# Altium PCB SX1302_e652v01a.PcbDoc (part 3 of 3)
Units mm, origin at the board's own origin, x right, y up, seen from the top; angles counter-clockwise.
Board outline 70.5 x 56 mm, 6 copper layers (Top Layer, MidLayer1 - GND, MidLayer2, MidLayer3, MidLayer4, Bottom Layer), stack 0.992 mm thick; 264 components, 191 nets, 862 pads, 1252 vias.
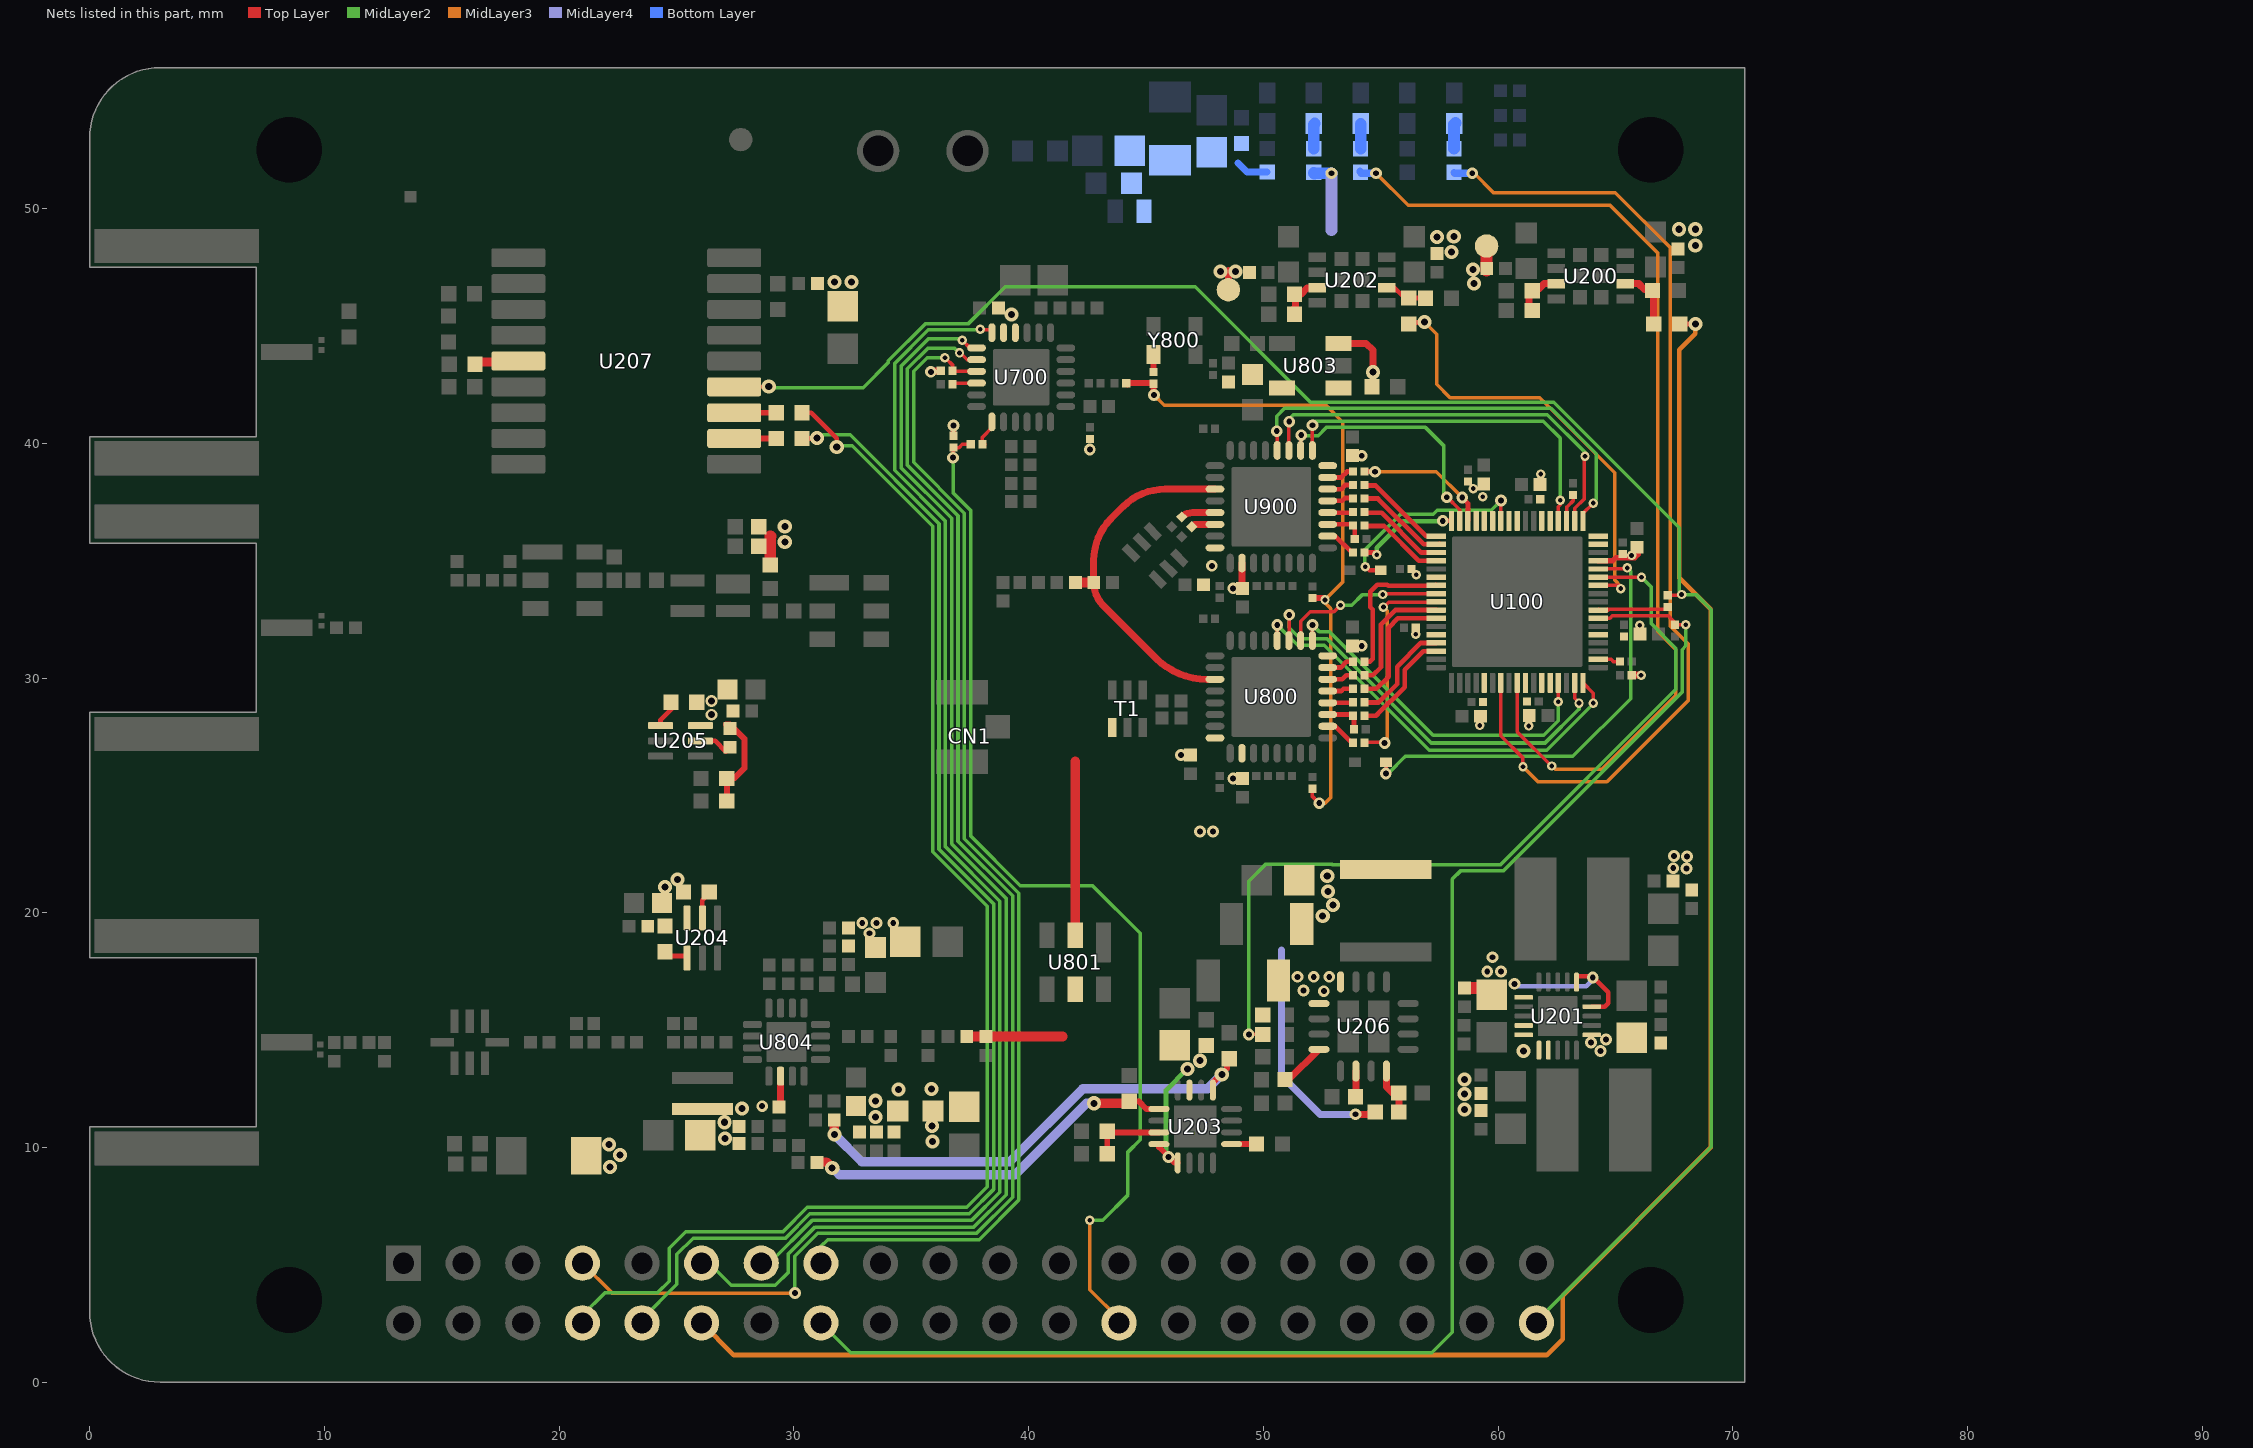
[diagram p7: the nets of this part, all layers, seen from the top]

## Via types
v1: diameter 0.6, hole 0.3, Top Layer to Bottom Layer, tented both sides, 827 vias
v2: diameter 0.5, hole 0.25, Top Layer to Bottom Layer, tented both sides, 168 vias
v3: diameter 0.6, hole 0.3, Top Layer to Bottom Layer, tented top, 86 vias
v4: diameter 0.4, hole 0.2, Top Layer to Bottom Layer, tented both sides, 59 vias
v5: diameter 0.6, hole 0.3, Top Layer to Bottom Layer, 48 vias
v6: diameter 0.6, hole 0.3, Top Layer to Bottom Layer, tented bottom, 21 vias
v7: diameter 0.5, hole 0.3, Top Layer to Bottom Layer, tented both sides, 18 vias
v8: diameter 0.5, hole 0.25, Top Layer to Bottom Layer, tented top, 16 vias
v9: diameter 0.5, hole 0.3, Top Layer to Bottom Layer, 5 vias
v10: diameter 0.5, hole 0.2, Top Layer to Bottom Layer, 4 vias

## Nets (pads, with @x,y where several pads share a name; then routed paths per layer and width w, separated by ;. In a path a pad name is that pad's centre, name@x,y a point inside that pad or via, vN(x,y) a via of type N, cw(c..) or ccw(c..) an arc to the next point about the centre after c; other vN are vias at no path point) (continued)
NetL800_2: L800.2 L801.1 U800.27 U900.27 | length 15.7
  Top Layer w0.3: L800.2@42.773,33.949 L800.2@42.773,34.073 ; U800.27@47.939,29.948 47.593,29.948 cw(c47.593,33.015) 45.425,30.847 43.18,33.091 cw(c44.162,34.073) L800.2@42.773,34.073 ; U900.27@47.939,38.048 45.816,38.048 ccw(c45.816,35.508) 44.02,37.305 43.517,36.802 ccw(c45.313,35.006) 42.773,35.006 L800.2@42.773,34.073
  Top Layer w0.42: L801.1@41.998,34.073 L800.2@42.773,34.073
NetR5_1: R5.1 R6.2 U206.4 | length 2.2
  Top Layer w0.3: U206.4@55.243,13.261 55.243,12.625 55.255,12.613 55.255,12.585 55.62,12.219 R6.2@55.77,12.219 ; R5.1@55.77,11.519 R6.2@55.77,12.219 ; R6.2@55.77,12.394 55.77,12.321 R6.2@55.77,12.219
NetR7_2: R7.2 U206.2 | length 1.1
  Top Layer w0.3: U206.2@53.943,13.261 53.943,12.249 R7.2@53.972,12.22
NetR8_2: R8.2 U206.16 | length 1.9
  Top Layer w0.3: R8.2@50.97,12.894 51.076,12.894 U206.16@52.368,14.186
NetR10_2: R10.2 R11.2 U801.5 | length 4.1
  Top Layer w0.42: R10.2@37.366,14.73 R11.2@38.191,14.729 41.455,14.73
NetR100_2: R100.2 U100.20 | length 1.2
  Top Layer w0.15: U100.20@62.915,36.698 62.915,37.266 62.985,37.336 62.985,37.339 63.192,37.546 R100.2@63.192,37.803
NetR102_1: R102.1 U100.2 | length 1
  Top Layer w0.15: U100.2@64.265,30.798 64.815,30.798 64.915,30.698 R102.1@65.19,30.698
NetR104_1: R104.1 TX_ON.1 | length 1.1
  Bottom Layer w0.5: R104.1@58.126,52.551 58.126,53.587 58.145,53.606 TX_ON.1@58.188,53.65
NetR106_1: R106.1 RX_ON.1 | length 1.1
  Bottom Layer w0.5: R106.1@54.143,52.551 54.143,53.592 RX_ON.1@54.15,53.599
NetR108_2: R108.2 U100.8 | length 3
  Top Layer w0.15: U100.8@64.29,32.923 U100.8@64.265,32.898 64.689,32.898 64.719,32.928 ; U100.8@64.644,32.93 64.645,32.928 64.719,32.928 ; R108.2@67.097,32.93 67.096,32.928 64.719,32.928
NetR110_1: R110.1 U100.44 | length 5.3
  Top Layer w0.2: R110.1@54.314,30.123 54.664,30.123 55.013,30.472 55.013,32.285 55.626,32.898 U100.44@57.365,32.898 U100.44@57.376,32.898
NetR111_1: R111.1 U100.45 | length 5.5
  Top Layer w0.2: R111.1@54.302,29.545 54.314,29.545 54.815,29.545 55.333,30.063 55.333,32.153 55.729,32.548 U100.45@57.365,32.548
NetR112_1: R112.1 U100.49 | length 4.7
  Top Layer w0.2: R112.1@54.314,28.398 54.806,28.398 54.861,28.453 ; 54.836,28.432 56.019,29.616 56.019,30.348 56.82,31.148 U100.49@57.365,31.148
NetR113_1: R113.1 U100.41 | length 6.3
  Top Layer w0.2: R113.1@54.314,30.698 54.542,30.698 54.659,30.816 54.659,32.922 54.556,33.025 54.556,33.685 54.849,33.978 55.279,33.978 55.318,33.939 U100.41@57.35,33.939 ; U100.41@57.35,33.963 U100.41@57.362,33.951
NetR114_1: R114.1 U100.48 | length 4.5
  Top Layer w0.2: R114.1@54.328,28.958 54.909,28.958 ; 54.912,28.961 55.699,29.748 55.699,30.485 56.712,31.498 U100.48@57.365,31.498
NetR115_1: R115.1 U100.43 | length 9.2
  Top Layer w0.15: R115.1@54.302,27.259 54.314,27.259 54.325,27.259 55.14,27.259 v2(55.166,27.234) ; v4(55.115,33.025) 55.14,33.025 55.344,33.228 57.365,33.228 57.376,33.228 57.38,33.233 U100.43@57.401,33.254
  Top Layer w0.2: R115.1@54.314,27.248 R115.1@54.325,27.259
  MidLayer3 w0.15: v4(55.115,33.025) 55.281,32.859 55.281,27.349 v2(55.166,27.234)
NetR120_1: R120.1 U100.35 | length 4
  Top Layer w0.2: R120.1@54.302,38.207 54.314,38.207 54.775,38.207 56.934,36.048 U100.35@57.365,36.048
NetR121_1: R121.1 U100.36 | length 4
  Top Layer w0.2: R121.1@54.302,37.648 R121.1@54.314,37.648 54.882,37.648 56.831,35.698 U100.36@57.365,35.698 57.5,35.698 U100.36@57.5,35.713
NetR122_1: R122.1 U100.38 | length 3.7
  Top Layer w0.2: R122.1@54.302,36.479 54.314,36.479 55.145,36.479 56.626,34.998 U100.38@57.365,34.998
NetR123_2: R123.2 U100.32 | length 5.7
  Top Layer w0.2: R123.2@54.314,38.798 v2@54.752,38.798 ; v2(58.471,37.692) 58.715,37.447 U100.32@58.715,36.698
  MidLayer2 w0.2: v2@54.734,38.816 v2@54.759,38.816
  MidLayer3 w0.15: v2(54.759,38.791) 57.372,38.791 v2(58.471,37.692)
NetR124_1: R124.1 U100.37 | length 3.8
  Top Layer w0.2: R124.1@54.314,37.073 R124.1@54.339,37.048 ; R124.1@54.328,37.038 55.039,37.038 56.729,35.348 U100.37@57.365,35.348
NetR125_2: R125.2 U100.34 | length 4.5
  Top Layer w0.2: R125.2@54.314,35.348 54.836,35.348 v4@54.874,35.348 ; v2@57.69,36.698 U100.34@58.015,36.698
  MidLayer2 w0.2: v4(54.836,35.26) 54.836,35.554 55.962,36.681 57.622,36.681 v2(57.64,36.698)
NetR200_1: R200.1 R202.2 U200.7 | length 1.9
  Top Layer w0.3: R202.2@61.313,45.835 61.313,46.505 R200.1@61.313,46.538 ; R200.1@61.313,46.585 61.451,46.585 61.746,46.585 61.96,46.799 U200.7@62.47,46.799
NetR201_1: R201.1 R207.2 U200.2 | length 2.8
  Top Layer w0.3: U200.2@65.42,46.799 65.991,46.799 66.24,46.55 66.579,46.55 R207.2@66.62,46.55 ; R207.2@66.62,46.566 R207.2@66.62,46.55 ; R201.1@66.621,45.105 66.62,45.107 66.62,46.512 R207.2@66.62,46.55 ; R207.2@66.672,46.55 R207.2@66.62,46.55
NetR203_1: R203.1 R206.2 U202.7 | length 1.8
  Top Layer w0.3: R206.2@51.203,45.633 51.377,45.806 51.377,46.353 51.377,46.368 51.619,46.368 51.864,46.613 52.283,46.613 U202.7@52.301,46.631
NetR204_1: R204.1 R213.2 U202.2 | length 1.9
  Top Layer w0.2: U202.2@55.251,46.631 55.583,46.631 55.937,46.277 R204.1@56.136,46.277 ; R204.1@56.115,46.314 56.215,46.213 56.241,46.187 56.739,46.187 56.821,46.269 R213.2@56.859,46.307
NetR205_1: R205.1 U204.2 | length 1.4
  Top Layer w0.2: U204.2@26.102,19.779 26.102,20.528 26.428,20.854 26.458,20.885 R205.1@26.572,20.885
NetR208_2: R208.2 VCCIO33.1 | length 1.1
  Bottom Layer w0.5: R208.2@52.152,52.551 52.152,53.582 52.173,53.604 VCCIO33.1@52.194,53.624
NetR211_1: R211.1 U207.3 | length 1.8
  Top Layer w0.25: U207.3@27.461,41.305 R211.1@29.245,41.305 29.263,41.305 cw(c29.263,41.272) R211.1@29.287,41.295
NetR212_1: R212.1 U207.2 | length 1.8
  Top Layer w0.25: U207.2@27.461,40.205 29.205,40.205 ccw(c29.205,40.285) R212.1@29.262,40.229
NetR214_1: R214.1 U205.4 | length 0.9
  Top Layer w0.2: U205.4@24.322,27.975 24.322,28.227 R214.1@24.792,28.697
NetR215_1: R215.1 U205.2 | length 1.3
  Top Layer w0.2: U205.2@26.022,27.325 26.645,27.325 27.099,26.871 R215.1@27.103,26.868
NetR216_1: R216.1 U204.4 | length 1
  Top Layer w0.2: R216.1@24.608,18.338 24.786,18.159 25.372,18.159 U204.4@25.452,18.079
NetR217_2: R217.2 U207.14 | length 1.8
  Top Layer w0.4: R217.2@16.466,43.463 18.261,43.463 U207.14@18.266,43.463
NetR218_2: R218.2 R219.1 U203.7 | length 3.1
  Top Layer w0.25: R219.1@43.352,9.783 43.349,9.786 43.349,10.64 43.356,10.647 U203.7@45.55,10.647
NetR220_1: R220.1 U203.13 | length 1.1
  Top Layer w0.2: R220.1@49.708,10.147 R220.1@49.712,10.15
  Top Layer w0.25: U203.13@48.65,10.147 R220.1@49.708,10.147
NetR704_1: R704.1 U700.16 | length 1
  Top Layer w0.15: R704.1@36.76,42.514 36.81,42.564 U700.16@37.785,42.564
NetR705_1: R705.1 U700.19 | length 1.1
  Top Layer w0.15: R705.1@38.035,39.964 38.035,40.264 38.435,40.664 U700.19@38.435,40.889 ; R705.1@38.135,39.939 R705.1@38.135,39.964
NetR815_2: R815.2 Y800.3 | length 0.7
  Top Layer w0.25: R815.2@45.314,43.091 Y800.3@45.314,43.788
POWER_EN: CN1.12 R201.2 | length 84.9
  Top Layer w0.2: R201.2@67.734,45.08 v1(68.403,45.08)
  MidLayer3 w0.2: CN1.12@26.071,2.535 27.442,1.163 62.078,1.163 62.75,1.835 62.75,3.692 69.063,10.006 69.063,32.936 67.72,34.279 67.72,43.985 68.403,44.668 v1(68.403,45.08)
PPS: CN1.40 R108.1 U207.4 | length 85.2
  Top Layer w0.15: U207.4@27.461,42.405 v1@28.898,42.405 ; R108.1@67.23,33.528 67.785,33.528 v4(67.815,33.558)
  MidLayer2 w0.15: v1@28.901,42.408 28.907,42.413 v1(28.931,42.413) ; v1@28.931,42.616 29.033,42.515 v1@29.18,42.368 ; v1@28.977,42.368 v1@29.18,42.368 ; CN1.40@61.647,2.484 61.647,2.535 61.647,2.613 69.075,10.041 69.075,32.915 68.432,33.558 v4@67.866,33.558 ; v4(67.815,33.558) v4@67.866,33.558 ; v1@29.18,42.368 32.949,42.368 34.025,43.443 34.025,43.513 35.615,45.103 37.442,45.103 39.01,46.67 47.097,46.67 52.01,41.757 62.363,41.757 67.717,36.403 67.717,33.707 67.84,33.584 v4@67.866,33.558
RADIO_A_CLK_32M: R115.2 U800.10 | length 1.3
  Top Layer w0.2: U800.10@52.739,27.948 53.064,27.948 R115.2@53.739,27.273
RADIO_A_CSN: U100.68 U800.20 | length 18.3
  Top Layer w0.15: U800.20@50.589,31.598 v2@50.589,32.263 ; U100.68@63.615,29.798 64.056,29.357 v4(64.056,28.936)
  MidLayer2 w0.15: v2@50.568,32.288 v2(50.594,32.263) 51.457,31.399 52.6,31.399 57.066,26.934 62.079,26.934 64.005,28.859 64.005,28.885 v4(64.056,28.936)
RADIO_A_IQ(0): R110.2 U800.14 | length 1.1
  Top Layer w0.2: U800.14@52.739,29.948 53.364,29.948 53.539,30.123 R110.2@53.814,30.123
RADIO_A_IQ(1): R111.2 U800.13 | length 1.1
  Top Layer w0.2: U800.13@52.739,29.448 53.314,29.448 53.414,29.548 R111.2@53.814,29.548
RADIO_A_IQ(2): R112.2 R813.1 U800.11 | length 1.7
  Top Layer w0.2: U800.11@52.739,28.448 53.764,28.448 R112.2@53.814,28.398 53.864,28.348 R813.1@53.864,27.823
RADIO_A_IQ(3): R113.2 U800.15 | length 1.2
  Top Layer w0.2: U800.15@52.739,30.448 53.289,30.448 53.539,30.698 R113.2@53.814,30.698
  Top Layer w0.25: U800.15@52.729,30.448 U800.15@52.739,30.448
RADIO_A_IQ(4): R114.2 U800.12 | length 1.1
  Top Layer w0.2: U800.12@52.739,28.948 53.789,28.948 R114.2@53.814,28.973
RADIO_A_MISO: U100.42 U800.18 | length 7.1
  Top Layer w0.15: U800.18@51.589,31.598 51.589,32.415 51.996,32.822 53.007,32.822 v4(53.286,33.101) ; v4(55.09,33.558) 55.129,33.598 U100.42@57.365,33.598
  MidLayer2 w0.15: v4(53.286,33.101) 53.769,33.101 54.226,33.558 v4(55.09,33.558) v4@55.115,33.558
RADIO_A_MOSI: U100.67 U800.19 | length 17.9
  Top Layer w0.15: U800.19@51.089,31.598 51.102,31.611 v2(51.102,32.695) 51.102,32.822 v2@51.127,32.847 ; U100.67@63.265,29.798 63.265,29.142 v4@63.421,28.986
  MidLayer2 w0.15: v2@51.089,32.708 v2(51.102,32.695) 51.102,32.137 51.569,31.669 52.712,31.669 57.147,27.235 61.999,27.235 63.44,28.676 ; 63.446,28.683 v4(63.446,28.936)
RADIO_A_RESET: D800.2 U100.13 | length 19.1
  Top Layer w0.15: v2@55.228,25.976 D800.2@55.228,26.408 ; U100.13@64.265,34.648 65.453,34.648 65.495,34.69 v4(65.495,34.693)
  MidLayer2 w0.15: v2(55.217,25.938) 55.318,25.938 56.045,26.665 ; 56.011,26.635 56.041,26.665 56.045,26.665 ; v4(65.495,34.693) 65.645,34.543 65.645,29.123 63.186,26.664 56.954,26.664 56.953,26.665 56.045,26.665
RADIO_A_SCK: U100.65 U800.17 | length 14.9
  Top Layer w0.15: U800.17@52.089,31.598 v2@52.089,32.223 ; v4@62.565,29.023 U100.65@62.565,29.798
  MidLayer2 w0.15: v2@52.118,32.288 v2(52.092,32.263) 52.372,31.984 52.804,31.984 57.227,27.56 61.942,27.56 62.557,28.175 v4(62.557,28.986)
RADIO_B_CLK_32M: R125.1 U900.10 | length 1.4
  Top Layer w0.2: U900.10@52.739,36.048 53.064,36.048 53.739,35.373 R125.1@53.814,35.373
RADIO_B_CSN: U100.18 U900.20 | length 19.3
  Top Layer w0.15: U900.20@50.589,39.698 50.589,40.518 v2@50.589,40.605 ; U100.18@63.615,36.698 63.615,37.019 v4(64.051,37.455)
  MidLayer2 w0.15: v2(50.568,40.518) 50.568,41.153 50.902,41.487 62.251,41.487 64.183,39.555 64.183,37.587 v4(64.051,37.455) ; v4(64.051,37.455) 64.023,37.427 63.995,37.455 v4(64.051,37.455)
RADIO_B_IQ(0): R120.2 U900.14 | length 1.1
  Top Layer w0.2: U900.14@52.739,38.048 53.314,38.048 53.489,38.223 R120.2@53.814,38.223
RADIO_B_IQ(1): R121.2 U900.13 | length 1.1
  Top Layer w0.2: U900.13@52.739,37.548 53.364,37.548 53.489,37.673 R121.2@53.814,37.673
RADIO_B_IQ(2): R122.2 R814.1 U900.11 | length 1.7
  Top Layer w0.2: U900.11@52.739,36.548 53.764,36.548 R122.2@53.814,36.498 53.889,36.423 R814.1@53.889,35.923
RADIO_B_IQ(3): R123.1 U900.15 | length 1.2
  Top Layer w0.2: U900.15@52.739,38.548 53.314,38.548 53.564,38.798 R123.1@53.814,38.798
  Top Layer w0.25: U900.15@52.714,38.548 U900.15@52.739,38.548
RADIO_B_IQ(4): R124.2 U900.12 | length 1.1
  Top Layer w0.2: U900.12@52.739,37.048 53.789,37.048 R124.2@53.814,37.073
RADIO_B_MISO: U100.33 U900.18 | length 10.7
  Top Layer w0.15: U900.18@51.589,39.698 v2@51.589,40.323 ; v2@57.821,37.712 58.36,37.173 58.365,37.173 U100.33@58.365,36.698
  MidLayer2 w0.15: v2(51.614,40.348) 51.636,40.327 52.331,40.327 52.681,40.677 56.904,40.677 57.693,39.888 57.693,37.827 v2(57.815,37.706)
RADIO_B_MOSI: U100.19 U900.19 | length 17.5
  Top Layer w0.15: U900.19@51.089,39.698 51.089,40.523 ; 51.089,40.473 v2@51.089,40.723 ; U100.19@63.265,36.698 63.265,37.228 63.665,37.628 v4@63.665,39.293
  MidLayer2 w0.15: v2(51.102,40.924) 51.102,41.051 51.267,41.217 62.101,41.217 63.7,39.617 v4(63.7,39.451)
RADIO_B_RESET: D900.2 U100.28 | length 9
  Top Layer w0.15: v4(54.339,34.748) 54.514,34.573 54.539,34.573 ; U100.28@60.115,36.698 60.115,37.555 v2(60.122,37.561)
  Top Layer w0.2: 54.539,34.598 D900.2@54.999,34.598
  MidLayer2 w0.15: v4@54.328,34.727 54.328,34.748 54.328,35.463 55.84,36.976 57.234,36.976 57.401,37.143 59.703,37.143 v2(60.122,37.561)
RADIO_B_SCK: U100.21 U900.17 | length 15.5
  Top Layer w0.15: U900.17@52.089,39.698 52.089,40.769 v2(52.092,40.772) ; U100.21@62.565,36.698 62.565,37.298 v4@62.651,37.384
  MidLayer2 w0.15: v2(52.092,40.772) 52.092,40.924 52.115,40.947 61.925,40.947 62.647,40.225 v4(62.647,37.58)
RADIO_CTRL(4): U100.16
RADIO_CTRL_(5): U100.17 | length 0.3
  Top Layer w0.15: U100.17@64.265,36.048 U100.17@64.615,36.048
RADIO_CTRL_(6): U100.22
RADIO_CTRL_(7): U100.26
RADIO_CTRL_(8): U100.27
RADIO_CTRL_(10): U100.29
RADIO_CTRL_(11): U100.31
RF_ON1: C810.1 U900.29 | length 1.5
  Top Layer w0.3: C810.1@46.525,36.863 cw(c46.973,36.416) 46.973,37.048 U900.29@47.939,37.048
RF_OP1: C809.1 U900.30 | length 1
  Top Layer w0.3: C809.1@46.944,36.453 cw(c47.174,36.223) 47.174,36.548 U900.30@47.939,36.548
RX_ON: R106.2 U100.60 | length 44.2
  Top Layer w0.15: U100.60@60.815,29.798 60.815,27.706 62.278,26.243 v4(62.291,26.255) ; v4@62.238,26.308 v4@62.291,26.256
  MidLayer3 w0.15: v2(54.801,51.505) 56.165,50.141 64.769,50.141 66.802,48.108 66.802,31.981 67.568,31.215 67.568,29.273 64.413,26.118 62.428,26.118 v4(62.291,26.255)
  Bottom Layer w0.3: R106.2@54.124,51.592 54.124,51.551 54.134,51.541 54.17,51.505 v2(54.801,51.505)
SX1261_BUSY: CN1.7 U700.14 | length 62.1
  Top Layer w0.15: v4(37.056,43.852) 37.091,43.852 37.38,43.564 U700.14@37.785,43.564
  MidLayer2 w0.15: v2(30.044,3.805) 30.04,3.809 30.04,5.37 31.015,6.346 37.782,6.346 39.317,7.881 39.317,20.723 36.993,23.047 36.993,36.917 34.835,39.075 34.835,43.177 35.699,44.041 36.858,44.041 37.051,43.848 37.056,43.843 v4(37.056,43.852)
  MidLayer3 w0.15: CN1.7@20.991,5.075 22.261,3.805 v2(30.044,3.805)
SX1261_DIO1: CN1.11 U700.13 | length 56.4
  Top Layer w0.15: v4(37.178,44.388) 37.502,44.064 U700.13@37.785,44.064
  MidLayer2 w0.15: CN1.11@26.071,5.075 26.391,5.075 27.336,4.13 29.206,4.13 29.77,4.694 29.77,5.482 30.903,6.616 37.67,6.616 39.047,7.993 39.047,20.611 36.723,22.935 36.723,36.805 34.565,38.963 34.565,43.289 35.721,44.445 37.121,44.445 v4(37.178,44.388)
SX1261_DIO2: CN1.13 U700.12 | length 53.5
  Top Layer w0.15: v4@37.935,44.831 37.944,44.831 38.435,44.831 38.45,44.831 U700.12@38.428,44.72
  MidLayer2 w0.15: CN1.13@28.601,5.075 CN1.13@28.611,5.075 28.957,5.075 30.796,6.914 37.586,6.914 38.777,8.105 38.777,20.499 36.453,22.824 36.453,36.694 34.295,38.851 34.295,43.401 35.727,44.833 37.917,44.833 v4(37.944,44.86)
SX1261_NRESET: CN1.15 R703.2 U700.15 | length 50.5
  Top Layer w0.15: v4(36.436,43.646) 36.452,43.646 36.509,43.589 v4@36.52,43.577 ; v4@36.51,43.589 36.76,43.339 R703.2@36.76,43.114 ; R703.2@36.76,43.089 R703.2@36.76,43.114 ; U700.15@37.785,43.064 36.81,43.064 36.772,43.102 R703.2@36.76,43.114
  MidLayer2 w0.15: CN1.15@31.151,5.075 31.151,5.79 31.437,6.076 37.894,6.076 39.587,7.769 39.587,20.835 37.263,23.159 37.263,37.029 35.105,39.187 35.105,43.065 35.686,43.646 v4(36.436,43.646)
SX1261_NSS: CN1.26 R702.2 R705.2 | length 45
  Top Layer w0.15: v2(36.78,39.39) 36.8,39.41 R702.2@36.8,39.826 ; R702.2@36.825,39.818 37.033,39.818 37.179,39.964 R705.2@37.535,39.964
  MidLayer2 w0.15: v2(36.78,39.39) 36.78,37.894 37.533,37.141 37.533,23.271 39.647,21.157 42.723,21.157 44.75,19.13 44.75,10.331 44.232,9.813 44.232,7.983 43.151,6.902 v4(42.61,6.902)
  MidLayer3 w0.15: v4@42.525,6.839 42.536,6.828 42.61,6.754 42.61,3.943 43.851,2.702 CN1.26@43.851,2.535 ; CN1.26@43.867,2.433 43.867,2.535 CN1.26@43.867,2.56
SX1302_LNA_REG_EN: R204.2 U100.11 | length 19
  Top Layer w0.15: U100.11@64.265,33.948 65.141,33.948 65.253,33.837 65.275,33.814 65.276,33.813 v4(65.229,33.813)
  Top Layer w0.2: R204.2@56.137,45.214 56.201,45.149 56.765,45.149 v1@56.805,45.19
  MidLayer2 w0.15: v1(56.868,45.164) v1@57.01,45.164
  MidLayer3 w0.15: v1(56.868,45.164) 57.384,44.647 57.384,42.511 57.951,41.944 61.766,41.944 64.964,38.746 64.964,34.177 65.229,33.912 v4(65.229,33.813) v4@65.252,33.837
SX1302_PA_REG_EN: R3.2 U100.12 | length 35.9
  Top Layer w0.15: v2(49.381,14.817) 49.382,14.819 R3.2@49.97,14.819 ; U100.12@64.265,34.298 v4(66.11,34.298)
  MidLayer2 w0.15: v2(49.381,14.817) 49.381,21.35 50.091,22.06 52.926,22.06 52.931,22.055 60.104,22.055 67.568,29.519 67.568,31.279 66.533,32.313 66.533,33.875 v4(66.11,34.298)
SX1302_RESET: CN1.16 R101.2 U100.7 | length 67
  Top Layer w0.15: U100.7@64.265,32.548 64.765,32.548 64.865,32.648 67.248,32.648 67.501,32.395 R101.2@67.501,32.33 ; R101.2@67.54,32.273 67.991,32.273 v4(67.997,32.278)
  MidLayer2 w0.15: CN1.16@31.151,2.535 32.427,1.259 57.174,1.259 58.05,2.135 58.05,21.44 58.395,21.785 60.216,21.785 67.838,29.407 67.838,31.215 67.997,31.373 v4(67.997,32.278)
SX1302_UART_RX: U100.64
SX1302_UART_TX: U100.63
TCXO_32M_O: C801.1 C901.2 R701.2 R815.1 | length 28.6
  Top Layer w0.15: C801.1@52.092,25.282 52.092,24.954 52.287,24.76 52.28,24.753 52.362,24.672 v2(52.381,24.672)
  Top Layer w0.25: R701.2@44.21,42.514 R701.2@44.16,42.564 45.291,42.564 R815.1@45.3,42.555 ; R815.1@45.259,42.514 R815.1@45.3,42.555 ; R815.1@45.309,42.564 R815.1@45.3,42.555 ; v2(45.341,42.061) 45.314,42.088 R815.1@45.314,42.54 R815.1@45.3,42.555 ; C901.2@52.118,33.406 52.524,33.406 52.613,33.317 v4@52.626,33.304
  MidLayer3 w0.15: v2(45.341,42.061) 45.785,41.618 52.671,41.618 53.388,40.9 53.388,34.093 v4(52.626,33.33) 52.626,33.203 52.867,32.962 52.867,24.912 52.626,24.672 v2(52.381,24.672)
TX_ON: R104.2 U100.58 | length 42.9
  Top Layer w0.15: U100.58@60.115,29.798 60.115,27.542 61.059,26.599 v4@61.059,26.243
  MidLayer3 w0.15: v2(58.901,51.505) 58.977,51.505 59.801,50.681 64.992,50.681 67.342,48.332 67.342,32.205 68.108,31.438 68.108,29.049 64.637,25.578 61.698,25.578 v4(61.059,26.218)
  Bottom Layer w0.3: R104.2@58.112,51.542 58.115,51.539 58.149,51.505 v2(58.901,51.505)
TX_PA: T1.1 U801.2 | length 7.4
  Top Layer w0.42: U801.2@41.987,19.045 41.987,26.44
UART_RXD_GPS: CN1.10 R212.2 | length 55
  Top Layer w0.2: R212.2@30.345,40.205 30.961,40.205 30.963,40.203 v1@30.989,40.178
  MidLayer2 w0.15: CN1.10@23.531,2.535 23.531,2.694 25.016,4.179 25.016,5.455 25.707,6.146 29.646,6.146 30.684,7.184 37.475,7.184 38.507,8.216 38.507,20.387 36.183,22.712 36.183,36.582 32.403,40.362 31.077,40.362 31.037,40.321 31.037,40.276 v1(30.989,40.229)
UART_TXD_GPS: CN1.8 R211.2 | length 57.6
  Top Layer w0.2: R211.2@30.345,41.305 30.738,41.305 31.827,40.216 v1(31.827,39.845)
  MidLayer2 w0.15: CN1.8@20.991,2.535 20.991,2.857 21.959,3.825 24.21,3.825 24.696,4.312 24.696,5.717 25.399,6.419 29.537,6.419 30.572,7.454 37.363,7.454 38.237,8.328 38.237,20.275 35.913,22.6 35.913,36.47 32.483,39.899 31.881,39.899 v1(31.827,39.845)
VCC5V: C8.2 C35.1 C47.1 C48.1 C201.1 C204.1 D2.2 D3.1 FB200.1 FB202.1 L8.2 R4.1 R14.2 R209.2 R210.2 RV1.2 U201.1 U201.4 U201.5 U201.6 U201.7 U201.11 U201.14 U201.16 U206.12 U206.13 | length 9.1
  Top Layer w0.2: U201.16@63.347,17.294 64.008,17.294 64.046,17.256 64.694,16.608 64.694,16.151 64.545,16.002 U201.14@63.989,16.002
  Top Layer w0.5: R209.2@58.564,16.801 59.739,16.801 59.802,16.801 C201.1@59.817,16.786
  MidLayer4 w0.2: v2(60.702,16.976) 60.808,16.871 63.75,16.871 64.033,17.154 v2(64.033,17.243)
  Bottom Layer w0.3: 48.917,51.948 49.31,51.555 R14.2@50.16,51.555
  other v1: 22.166,9.172 22.591,9.687 22.134,10.134 61.087,14.119 58.011,48.148 68.399,48.435 57.401,48.797 58.112,48.813 67.713,49.12 68.399,49.12
  other v2: 64.363,14.119 63.957,14.475 64.592,14.602 52.576,16.664 51.712,16.69 51.458,17.274 52.144,17.274 52.804,17.274 59.537,17.497 60.122,17.497 59.766,18.107
VCC_APC1: C210.1 R9.2 U203.1 | length 20.7
  Top Layer w0.25: U203.1@47.85,12.447 47.85,12.761 48.215,13.126 48.452,13.363 48.452,13.722 C210.1@48.517,13.787
  Top Layer w0.4: v1@31.719,10.568 R9.2@31.719,11.171
  MidLayer4 w0.4: v1(31.725,10.561) 32.89,9.397 39.201,9.397 42.312,12.508 47.625,12.508 v1(48.229,13.112)
VCC_APC2: C211.1 R1.2 U203.5 | length 16.2
  Top Layer w0.25: C211.1@44.283,11.972 44.691,11.972 45.016,11.647 U203.5@45.55,11.647
  Top Layer w0.4: R1.2@30.982,9.444 31.02,9.406 31.041,9.385 31.387,9.385 v1(31.634,9.139) ; v1(42.794,11.888) 44.199,11.888 C211.1@44.283,11.972
  MidLayer4 w0.4: v1(31.634,9.139) 31.931,8.843 39.42,8.843 42.465,11.888 v1(42.794,11.888)
VCCCORE12: C100.2 C101.2 C102.2 C103.2 C106.2 C108.2 C113.2 C221.2 FB208.2 U100.5 U100.23 U100.40 U100.56 | length 0.1
  Top Layer w0.23: C108.2@59.362,28.978 C108.2@59.415,29.031
  other v1: 58.56,11.618 58.56,12.279 58.56,12.896
  other v4: 59.215,27.985 66.04,32.248 56.512,34.397 61.822,38.69
VCCIO33: C104.2 C105.2 C107.2 C109.2 C110.2 C111.2 C112.2 C208.1 C209.1 C212.1 C213.1 C219.1 C220.2 C222.1 C223.1 FB1.1 FB207.2 R2.2 R15.2 R103.2 R205.2 R208.1 R214.2 R215.2 R216.2 U100.14 U100.30 U100.47 U100.61 U203.3 U203.8 U203.9 U204.3 U205.3 | length 15
  Top Layer w0.23: U203.8@45.55,10.147 45.55,10.016 46.219,9.347 U203.9@46.35,9.347 ; U100.14@64.265,34.998 64.883,34.998 65.013,35.128 65.819,35.128 65.972,35.281
  Top Layer w0.25: R2.2@27.103,25.903 R2.2@27.145,25.903 ; R215.2@27.103,28.028 27.28,28.028 27.893,27.415 27.893,26.161 27.482,25.751 27.145,25.751 R2.2@27.145,25.725 R15.2@27.145,24.815
  Top Layer w0.3: R103.2@65.69,30.123 v4@66.065,30.123
  MidLayer2 w0.2: v2(45.959,9.595) 45.855,9.698 45.855,12.449 v1(46.76,13.354)
  MidLayer4 w0.5: v2(52.901,51.505) 52.901,49.08 52.903,49.078
  Bottom Layer w0.5: R208.1@52.143,51.516 52.169,51.491 52.183,51.505 v2(52.901,51.505)
  other v1: 47.307,13.701 24.504,21.098 25.035,21.419 31.723,46.873 32.463,46.873
  other v2: 68.021,21.891 67.462,21.904 68.046,22.399 67.488,22.424 47.303,23.463 47.857,23.463
  other v4: 61.299,27.962 66.09,30.123 56.49,31.873 65.685,35.225 59.34,37.723 58.94,38.073
  other v7: 26.493,28.443 26.493,29.027
VDD_D_3.0_TCXO: C817.2 FB801.1 U803.5
VDD_RF_125x: C718.2 C800.2 C806.2 C808.2 C811.2 C900.2 C906.2 C908.2 FB201.2 P200.1 R702.1 R703.1 R713.1 U700.10 U700.11 U800.2 U800.16 U800.32 U803.1 U803.3 U900.2 U900.16 U900.32 | length 5.8
  Top Layer w0.2: R702.1@36.8,40.326 v2@36.8,40.733
  Top Layer w0.3: v2@35.86,43.089 R703.1@36.26,43.089 ; v2(48.714,33.823) C906.2@49.114,33.823 49.089,33.848 U900.2@49.089,34.898 ; U803.3@53.196,44.255 54.379,44.255 54.664,43.97 v1(54.664,43.029)
  Top Layer w0.5: FB201.2@59.509,47.365 59.509,47.452 P200.1@59.509,48.355
  other v1: 39.263,45.482 58.976,46.8 58.925,47.41
  other v2: 48.714,25.723 46.489,26.723 54.189,31.373 47.805,34.781 54.189,39.473 42.61,39.737 36.8,40.758 35.834,43.044
VDD_RF_LNA: C43.2 C44.2 FB203.2 L12.2 P201.1 | length 2.1
  Top Layer w0.3: P201.1@48.511,46.518 P201.1@48.511,46.538 48.511,47.318 48.511,47.363
  Top Layer w0.5: L12.2@28.997,34.813 28.997,35.621 28.997,36.041 29.004,36.048
  other v1: 29.613,35.794 29.613,36.454 48.181,47.318 48.816,47.318
VDD_RF_PA: C9.2 C10.2 C22.2 C37.2 C38.2 C39.2 L1.2 L2.1 L10.1 R5.2 | length 9.9
  Top Layer w0.3: C37.2@34.275,18.356 C37.2@34.287,18.344 ; v2@53.92,11.456 v2(53.92,11.419) 54.483,11.419 R5.2@54.573,11.508
  MidLayer4 w0.3: 50.778,18.406 50.778,13.059 52.418,11.419 v2(53.92,11.419)
  other v1: 35.913,10.267 35.887,10.927 35.862,12.502 52.528,19.861 52.96,20.328 52.746,20.917 52.721,21.565
  other v2: 33.22,19.13 32.915,19.563 33.525,19.563 34.236,19.563
VDDPA_A2: C12.2 C13.2 C14.2 C19.2 C23.2 C24.2 C25.2 L2.2 L3.2 L4.2 U804.14 | length 1.3
  Top Layer w0.3: C19.2@29.435,11.715 29.435,11.73 U804.14@29.435,13.045
  other v1: 27.073,10.394 27.048,11.079 33.474,11.308 27.785,11.664 33.474,11.994 34.465,12.476
  other v2: 28.648,11.765
pads on no net: "Fiducial Mark1.1" CN1.0 CN1.1 CN1.17 CN1.18 CN1.22 CN1.27 CN1.28 CN1.32 CN1.35 CN1.37 T1.6 T800.6 U100.10 U200.1 U200.4 U200.5 U202.1 U202.4 U202.5 U203.4 U203.15 U203.16 U207.5 U207.13 U207.15 U207.16 U207.17 U207.18 U700.4 U700.6 U700.23 U700.24 U800.6 U800.21 U800.22 U800.23 U800.24 U804.7 U804.13 U805.2 U805.6 U900.6 U900.21 U900.22 U900.23 U900.24

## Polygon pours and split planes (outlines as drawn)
VDD_RF_LNA on MidLayer4 "MidLayer3-No Net" (solid, pour order 200): 49.038,47.699 46.91,47.699 35.902,47.699 34.185,45.982 34.185,39.21 31.783,36.808 29.446,36.808 29.279,36.641 29.279,35.63 29.47,35.438 29.784,35.438 29.983,35.638 29.983,36.113 30.093,36.223 32.438,36.223 35.024,38.808 35.024,45.349 36.674,46.999 48.964,46.999 49.134,47.168 49.134,47.604
VDD_RF_PA on MidLayer4 "MidLayer4-No Net 1" (solid, pour order 70): 35.303,18.318 35.303,10.334 35.701,9.936 36.167,9.936 36.268,10.038 36.268,18.725 35.709,18.725
VDDPA_A2 on MidLayer4 "MidLayer4-No Net 1" (solid, pour order 68): 33.83,12.832 32.992,11.994 27.404,11.994 26.718,11.308 26.718,10.292 26.946,10.063 27.2,10.063 27.404,10.267 27.404,10.826 27.556,10.978 33.677,10.978 33.982,11.283 33.982,11.867 34.185,12.07 34.643,12.07 34.795,12.222 34.795,12.756 34.719,12.832
VDD_RF_PA on MidLayer4 "MidLayer4-No Net" (solid, pour order 262): 52.226,19.036 53.27,20.08 53.27,22.091 53.206,22.155 52.328,22.155 52.184,22.011 52.184,20.659 51.342,19.817 49.857,19.817 32.687,19.817 32.458,19.588 32.458,18.953 32.763,18.649 34.806,18.649 35.365,18.09 49.705,18.09 51.28,18.09
VDD_RF_125x on MidLayer4 "MidLayer4-No Net 3" (solid, pour order 158): 52.807,43.062 53.556,43.81 57.01,43.81 58.595,45.395 58.595,47.548 58.777,47.73 59.149,47.73 59.357,47.522 59.357,44.946 57.295,42.885 55.184,42.885 54.89,42.591 54.89,39.995 52.807,39.995
VDD_RF_125x on MidLayer4 "MidLayer4-No Net 3" (solid, pour order 336): 35.423,40.821 35.81,40.434 36.916,40.434 37.109,40.627 37.109,40.896 36.943,41.061 36.034,41.061 35.887,41.209 35.887,42.689 36.133,42.935 36.133,44.214 37.083,45.164 41.536,45.164 42.034,44.666 42.034,39.902 42.477,39.459 42.765,39.459 43.202,39.896 43.202,42.575 43.446,42.819 53.65,42.819 54.119,43.288 53.597,43.81 43.307,43.81 42.788,44.329 42.788,44.971 41.896,45.859 36.969,45.859 35.603,44.493 35.603,43.249 35.563,43.209 35.423,43.069 35.423,42.601
VDD_RF_125x on MidLayer4 "MidLayer4-No Net 4" (solid, pour order 348): 46.112,26.482 47.136,25.458 54.193,25.458 54.89,26.155 54.89,40.931 52.807,40.931 52.807,34.742 52.411,34.346 47.597,34.346 47.574,34.304 47.574,33.508 50.822,33.508 51.139,33.191 51.418,33.191 53.442,31.166 53.442,26.653 53.193,26.404 47.533,26.404 46.78,27.158 46.327,27.158 46.112,26.944
VCCIO33 on MidLayer4 "MidLayer4-No Net" (solid, pour order 8): 58.519,38.077 59.141,37.455 64.153,37.455 64.919,36.688 64.919,30.002 64.259,29.342 57.706,29.342 56.918,30.129 56.918,31.946 56.633,32.231 56.049,32.231 55.751,31.932 55.751,29.265 57.315,27.701 65.265,27.701 67.188,25.778 67.188,21.76 67.356,21.593 68.248,21.593 68.425,21.77 68.425,26.446 66.84,28.031 66.84,36.87 65.003,38.708 58.765,38.708 58.519,38.461
VCCIO33 on MidLayer4 "MidLayer4-No Net 1" (solid, pour order 38): 44.117,23.729 27.509,23.729 27.509,22.814 68.12,22.814 68.12,23.602 67.993,23.729
VCCIO33 on MidLayer4 "MidLayer3-No Net" (solid, pour order 188): 26.239,29.281 26.722,29.281 26.798,29.205 26.798,24.582 27.661,23.719 28.195,23.719 28.195,22.814 27.499,22.814 26.188,24.125 26.188,29.23
VCCIO33 on MidLayer4 "MidLayer3-No Net" (solid, pour order 202): 60.551,37.83 60.405,37.976 60.405,47.584 59.196,48.793 33.763,48.793 32.814,47.844 32.814,46.735 32.613,46.534 31.55,46.534 31.337,46.747 31.337,48.408 32.97,50.041 59.563,50.041 61.541,48.063 61.541,38.026 61.345,37.83
GND on MidLayer4 "MidLayer3-No Net" (solid, pour order 352): 70.5,56.01 70.5,0 0,0 0,56.007
VCC5V on Bottom Layer "Bottom Layer-No Net" (solid, pour order 294): 46.312,48.575 45.193,48.575 44.596,49.172 44.596,50.793 44.445,50.944 44.445,51.456 45.754,51.456 45.849,51.361 45.849,50.423 46.312,49.961
NetC34_1 on Bottom Layer "MidLayer2-No Net" (solid, pour order 270): 14.695,10.708 15.074,10.708 15.172,10.61 15.172,2.514 15.127,2.47 14.437,2.47 14.248,2.658 14.248,10.425 14.532,10.708
VCCIO33 on Bottom Layer "MidLayer2-No Net" (solid, pour order 266): 48.072,23.728 48.141,23.659 48.141,23.322 47.816,22.996 47.816,13.774 47.069,13.027 46.633,13.027 46.425,13.235 46.425,13.576 47.108,14.259 47.108,23.207 47.016,23.299 47.016,23.64 47.104,23.728
VCC5V on Bottom Layer "MidLayer4-No Net 1" (solid, pour order 52): 49.375,53.116 49.502,52.989 49.502,51.643 49.349,51.491 46.089,51.491 45.59,50.992 45.59,50.678 43.914,50.678 43.888,50.703 43.888,53.091 43.914,53.116
VCC5V on Bottom Layer "MidLayer4-No Net 3" (solid, pour order 142): 46.073,50.052 45.669,49.648 45.669,48.903 45.997,48.575 57.017,48.575 57.37,48.222 57.37,48.018 57.55,47.838 58.148,47.84 58.706,48.398 67.173,48.398 67.383,48.188 67.383,48.025 67.414,47.995 68.639,47.995 68.893,48.249 68.893,49.525 68.366,50.052
VCC5V on Bottom Layer "MidLayer4-No Net 1" (solid, pour order 48): 61.516,13.619 63.522,13.619 63.689,13.786 63.689,14.635 63.923,14.869 64.862,14.869 64.862,13.714 64.664,13.516 63.841,12.693 61.452,12.693 61.313,12.554 61.313,7.142 60.349,6.178 42.973,6.178 42.973,8.477 59.166,8.477 59.166,18.084 59.461,18.379 59.946,18.379 61.405,16.92 61.405,13.73
VCC5V on Bottom Layer "Top Layer-No Net" (solid, pour order 254): 51.347,17.581 52.958,17.581 53.071,17.469 53.071,16.682 52.836,16.448 52.836,7.438 52.463,7.065 51.029,7.065 51.029,17.329 51.282,17.581 51.33,17.581
VCC5V on Bottom Layer "MidLayer2-No Net" (solid, pour order 278): 21.818,8.996 21.956,8.858 24.632,6.182 43.085,6.182 43.487,6.584 44.632,6.584 44.66,6.612 44.66,7.757 44.66,8.476 42.088,8.476 41.369,7.757 41.115,7.757 24.994,7.757 22.303,10.448 21.993,10.448 21.818,10.274
VCC5V on Bottom Layer "Bottom Layer-No Net" (solid, pour order 290): 66.479,27.8 65.063,26.384 61.278,26.384 59.169,24.275 59.169,16.363 60.152,15.38 61.405,15.38 61.405,23.192 62.286,24.073 66.235,24.073 69.204,27.042 69.204,49.211 68.878,49.537 66.479,49.537
VCCCORE12 on Bottom Layer "MidLayer4-No Net" (solid, pour order 324): 57.655,11.947 58.326,11.277 58.976,11.277 58.976,27.454 59.696,28.174 65.478,28.174 66.326,29.021 66.326,37.093 64.526,38.892 61.723,38.892 61.601,38.771 61.601,38.41 61.964,38.047 63.939,38.047 64.526,37.459 64.526,30.003 64.117,29.594 57.708,29.594 57.223,30.079 57.223,34.346 56.918,34.651 56.36,34.651 55.928,34.219 55.928,29.554 57.655,27.827
GND on Bottom Layer "MidLayer3-No Net" (solid, pour order 340): 70.5,56.01 70.5,0 0,0 0,56.007
VCCCORE12 on Top Layer "MidLayer4-No Net 2" (solid, pour order 314): 59.53,29.183 59.53,27.99 59.308,27.769 59.135,27.769 58.987,27.916 58.987,28.516 59.188,28.717 59.188,29.07 59.301,29.183
VDD_RF_125x on Top Layer "Top Layer-No Net 2" (solid, pour order 288): 52.768,42.676 54.064,42.676 54.335,42.947 54.335,43.175 54.52,43.36 54.793,43.36 55.032,43.118 55.032,42.158 54.904,42.03 52.769,42.03
VCC5V on Top Layer "MidLayer2-No Net" (solid, pour order 272): 20.506,10.458 22.293,10.458 22.903,9.848 22.903,9.461 22.302,8.861 20.509,8.861
NetC34_1 on Top Layer "MidLayer2-No Net" (solid, pour order 268): 15.922,9.246 15.922,10.486 15.305,10.489 15.057,10.737 14.627,10.737 14.419,10.529 14.419,8.878 14.569,8.728 15.204,8.728 15.456,8.98 15.922,8.98
VCCIO33 on Top Layer "MidLayer2-No Net" (solid, pour order 264): 46.724,12.31 46.726,12.931 45.672,13.984 45.672,14.458 45.908,14.693 45.924,14.677 47.877,14.677 47.875,13.83 46.974,12.93 46.974,12.313
VDD_RF_PA on Top Layer "MidLayer2-No Net" (solid, pour order 258): 51.138,19.151 51.138,20.457 50.862,20.734 50.862,22.027 51.079,22.244 55.445,22.244 55.647,22.042 55.647,21.486 55.606,21.445 54.642,21.447 52.11,18.907 51.138,18.907
NetL1_1 on Top Layer "MidLayer2-No Net" (solid, pour order 256): 53.792,17.426 53.269,17.949 53.269,18.376 53.521,18.628 56.203,18.628 56.203,18.306 55.392,17.494 55.392,16.686 55.316,16.61 53.85,16.61 53.793,16.667
NetC215_1 on Top Layer "MidLayer3-No Net" (solid, pour order 204): 27.027,46.41 30.374,46.41 30.503,46.538 30.503,47.102 30.398,47.207 27.115,47.207 27.027,47.119
VCCIO33 on Top Layer "MidLayer3-No Net" (solid, pour order 206): 30.792,47.211 32.709,47.211 32.814,47.106 32.814,45.233 32.738,45.158 31.367,45.158 30.732,45.792 30.732,47.151
VCCCORE12 on Top Layer "Top Layer-No Net" (solid, pour order 252): 58.15,11.476 58.318,11.308 59.551,11.308 59.552,12.573 58.968,12.576 58.878,12.666 58.878,13.069 58.719,13.227 58.318,13.227 58.15,13.06
VCC5V on Top Layer "MidLayer3-No Net" (solid, pour order 192): 45.792,8.352 47.159,8.352 47.296,8.489 47.296,9.146 46.418,10.016 45.721,10.016 45.626,9.922 45.626,8.444 45.719,8.351 45.764,8.351
GND on Top Layer "MidLayer3-No Net" (solid, pour order 332): 70.5,56.003 70.5,-0.007 0,-0.007 0,56
GND on MidLayer1 - GND "MidLayer3-No Net" (solid, pour order 240): 70.5,56.01 70.5,0 0,0 0,56.007
GND on MidLayer3 "MidLayer3-No Net" (solid, pour order 300): 70.5,56.01 70.5,0 0,0 0,56.007
GND on MidLayer2 "MidLayer3-No Net" (solid, pour order 298): 70.5,56.01 70.5,0 0,0 0,56.007

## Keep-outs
Keep-Out Layer:
  lines w0.1: 8.001,0.005 70.501,0.005 ; 8.001,56.005 70.501,56.005 ; 70.501,0.005 3.001,0.005 cw(c3.001,3.005) 0.001,3.005 0.001,53.005 cw(c3.001,53.005) 3.001,56.005 70.501,56.005 ; 70.501,0.005 70.501,56.005

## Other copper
Top Layer:
  drawing of 258 lines, arcs and shapes, not listed
MidLayer4:
  region net VCCIO33: 24.617,21.797 25.212,21.797 27.278,23.863 27.547,23.594 27.547,22.88 25.43,20.763 24.371,20.763 24.186,20.952 24.186,21.364
  region net VDD_RF_125x: 47.984,35.135 48.108,35.012 48.108,34.435 48.311,34.232 48.311,33.508 47.575,33.508 47.49,33.593 47.49,35.076 47.549,35.135
Bottom Layer:
  rectangle net GND: 49.197,53.32 49.679,54.361
  rectangle net GND: 46.25,54.209 50.518,55.021
  rectangle net NetF200_2: 40.768,51.836 43.157,53.081
  region net NetF200_1: 37.466,53.487 39.777,53.487 40.184,53.081 40.184,51.811 39.828,51.455 36.704,51.455 36.424,51.735 36.424,53.183 36.729,53.487

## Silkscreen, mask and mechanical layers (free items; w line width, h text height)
Top Overlay:
  lines w0.1: 31.892,24.948 32.51,24.948 ; 32.193,24.529 32.193,25.248 ; 32.985,45.855 33.603,45.855 ; 33.287,45.435 33.287,46.155 ; 34.549,17.563 35.167,17.563 ; 34.85,17.143 34.85,17.863
  text "SX1302 CoreCell Gateway SX1255/7/8 Front-Ends" at 21.841,54.158 h1
  text "PCB_E652V01A 1121" at 43.406,52.329 h0.8
  text "2x SX1257" at 34.757,30.392 h1
  text "SX1302" at 62.938,26.548 h1
Bottom Overlay:
  text "SX1302 CoreCell Gateway" at 31.471,54.503 h1.1
  text "PCB_E652V01A 1121" at 31.823,52.253 h1.1
  text "GPS" at 3.944,50.206 h1
  text "RFI" at 7.707,25.559 h1
  text "RFO" at 4.358,7.529 h1
Top Solder:
  rectangle: 63.098,45.827 64.797,48.422
  rectangle: 52.928,45.654 54.626,48.256
Bottom Solder:
  rectangle: 27.026,12.502 33.83,18.242
  rectangle: 47.834,34.803 52.835,39.796
  rectangle: 47.834,26.682 52.835,31.699
  rectangle: 37.682,40.804 41.687,44.5
  rectangle: 61.567,13.899 63.573,17.353
  rectangle: 52.651,9.215 57.43,11.994
  rectangle: 13.154,12.502 28.728,17.252
  rectangle: 52.706,45.613 54.687,48.357
  rectangle: 62.993,45.842 64.898,48.382
  region: 63.59,36.023 58.04,36.023 58.04,30.473 63.59,30.473
Mechanical 1:
  rectangle: 21.451,13.939 22.467,14.117
  rectangle: 23.234,13.953 24.885,14.131
  rectangle: 26.311,13.996 27.835,14.174
  lines w0.01: 0.001,51.005 16.406,51.005 ; 13.175,50.508 13.175,51.156
Mechanical 2:
  lines w1: 14.5,53.04 14.526,53.015 ; 20.088,53.066 20.139,53.015
Mechanical 3:
  region: 1.551,16.355
  lines w0.02: 1.251,16.355 1.851,16.355 ; 1.551,16.055 1.551,16.655
  text "Origin(0;0)" at -23.6,14.762 h1
Mechanical 14:
  lines w0.1: 0.001,2.985 0.001,10.885 ; 0.001,3.005 ccw(c3.001,3.005) 3.001,0.005 ; 0.001,18.085 0.001,28.545 ; 0.001,35.745 7.101,35.745 7.101,28.545 0.011,28.545 ; 0.001,35.755 0.001,40.275 7.101,40.275 7.101,47.49 7.096,47.495 0.001,47.495 0.001,52.995 ; 0.001,53.005 cw(c3.001,53.005) 3.001,56.005 70.501,56.005 70.501,0.005 3.001,0.005 ; 0.011,10.885 7.101,10.885 7.101,18.085 0.011,18.085 ; 3.001,0.005 3.001,0.005
Mechanical 15:
  circle w0.1: c8.501,52.505 r3.606
  lines w0.01: 1.676,16.605 1.926,16.605 ; 1.801,16.48 1.801,16.73

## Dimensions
3.001,0.005 to 8.001,56.105 on Mechanical 3
0.001,10.885 to 70.501,0.005 on Mechanical 3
